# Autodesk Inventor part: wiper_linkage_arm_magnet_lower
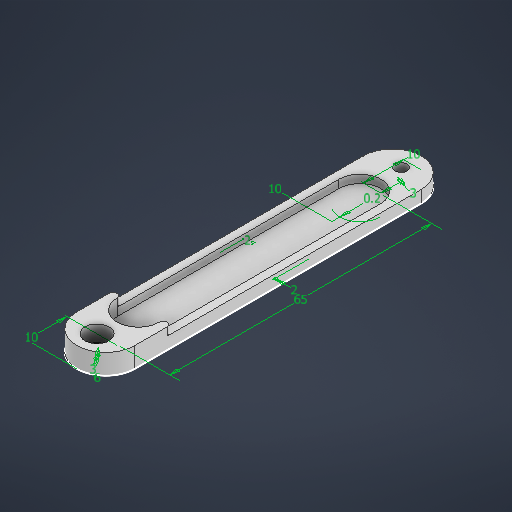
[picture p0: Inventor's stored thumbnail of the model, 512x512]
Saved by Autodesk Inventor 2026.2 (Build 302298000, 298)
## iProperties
Created: 2026-03
Part Number: wiper_linkage_arm_magnet_lower
Material: Generic
Document SubType Name: Modeling
Designer: Tathagata Sikdar
Density: 1 g/cm^3
Appearance: Default
Author: Tathagata Sikdar
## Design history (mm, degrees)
sketch "Sketch1"
  geometry: L1 (0, 0)-(0, -65); L2 (-5, -5)-(-5, -60); L3 (5, -60)-(5, -5); L4 (5.2, -60)-(5.2, -5); L5 (-5.2, -5)-(-5.2, -60); L6 (-7.2, 3)-(-7.2, -68); L7 (7.2, -68)-(7.2, 3); L8 (0, -75.2)-(0, -65.2); L9 (0, 0.2)-(0, 10.2); C1 r 1.5 at (0, -70.2); C2 r 1.5 at (0, 5.2); C3 r 3 at (0, 5.2); A1 r 5 centre (0, -5) between (5, -5) and (-5, -5); A2 r 5 centre (0, -60) between (-5, -60) and (5, -60); A3 r 5.2 centre (0, -5) between (5.2, -5) and (-5.2, -5); A4 r 5.2 centre (0, -60) between (-5.2, -60) and (5.2, -60); A5 r 7.2 centre (0, 3) between (7.2, 3) and (-7.2, 3); A6 r 7.2 centre (0, -68) between (-7.2, -68) and (7.2, -68); A7 r 1 centre (-6.2, -5) between (-7.2, -5) and (-5.2, -5); A8 r 1 centre (6.2, -5) between (5.2, -5) and (7.2, -5); 4 further points
  constraints: 22 point on circle, 20 end point, 12 tangent, 11 centre point, 4 midpoint, 4 point on line, 4 vertical, 3 coincident, 2 parallel, 3 other
  dimensions: "d0" = 65 distance of L1.start L1.end; "d1" = 10 diameter of A2; "d2" = 0.2 radial gap between concentric circles of A2 A4; "d8" = 2 distance between parallel lines of L6 L5; "d9" = 2 distance from line of point (7.2, -32.5) L4; "d10" = 10 distance of L8.start L8.end; "d11" = 10 distance of L9.end L9.start; "d12" = 3 diameter of C1; "d13" = 3 diameter of C2; "d14" = 6 diameter of C3
extrude "Extrusion3" new body sketch "Sketch1" distance "d15" = 1; taper "d16" = 0 deg
extrude "Extrusion4" join sketch "Sketch1" stored distance "d17" = 2; taper "d18" = 0 deg
extrude "Extrusion5" join sketch "Sketch1" stored distance "d19" = 2; taper "d20" = 0 deg
body "Solid2"
